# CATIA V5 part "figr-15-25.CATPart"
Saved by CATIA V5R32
Part number: Part1
Bounding box of the stored display mesh (mm): x -50 to 50, y -25 to 26, z -24 to 1
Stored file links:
  D:\PROJECTS\Project 2022\CATIA V5 6R 2022\Resources\Part Files\c15_catia_v5_6r2022_prt\figr-15-25.CATPart
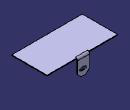
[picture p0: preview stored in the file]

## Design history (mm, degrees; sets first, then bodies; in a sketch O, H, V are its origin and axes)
SheetMetalParameters1: Thickness 1, BendRadius 2, KFactor 0.400515 {= log(min(100,max(20*SheetMetalParameters1.BendRadius,SheetMetalParameters1.Thickness)/SheetMetalParameters1.Thickness))/log(100)/2}, ReliefRadialLength 1, ReliefAxialLength 2, MinimumBendRadius 0
Body1 (main body)
  Sketch1 on xy-plane, origin (0, 0, 0), H (1, 0, 0), V (0, 1, 0)
    line L1 (-50, 25) -> (50, 25)
    line L2 (50, 25) -> (50, -25)
    line L3 (50, -25) -> (-50, -25)
    line L4 (-50, -25) -> (-50, 25)
    length L1 = 100
    distance V L2 = 50
    length L2 = 50
    distance H L3 = 25
    horizontal: L1 H, L3 H
    vertical: L2 V, L4 V
  Wall1: Thickness 1, Profile Sketch1
  Sketch2 on face of Wall1, origin (50, 25, 0), H (-1, 0, 0), V (0, 0, 1)
    line L1 (42.3549, 1) -> (42.3549, -19)
    point P2 (42.3549, -19)
    line L2 (42.3549, -19) -> (47.3549, -24)
    point P3 (47.3549, -24)
    line L3 (47.3549, -24) -> (54.3549, -24)
    point P4 (54.3549, -24)
    line L4 (54.3549, -24) -> (59.3549, -19)
    point P5 (59.3549, -19)
    line L5 (59.3549, -19) -> (59.3549, 1)
    line L6 (59.3549, 1) -> (42.3549, 1)
    reference projected line E1 (100, 1) -> (0, 1) from edge [face of Wall1 | face of Wall1]
    ellipse A1 centre (50.1164, -15.2153) semi-axes 5.0583, 2.1402 rotation 0
    length L5 = 20
    length L1 = 20
    length L3 = 7
    distance P4 L5 = 5
    distance P2 P3 H = 5
    distance L3 P5 = 5
    vertical: L1 V, L5 V
    horizontal: L3 H, L6 H
    coincidence: L6 E1
    parallelism: A1 L3
  d_NewWallOnEdge1: NewWallOnEdge_Edge edge [face of Wall1 | face of Wall1], NewWallOnEdge_WallProfile Sketch2, NewWallOnEdge_Length 100, NewWallOnEdge_HeightLimitOffset 0, NewWallOnEdge_WidthOffset1 0, NewWallOnEdge_WidthOffset2 0, NewWallOnEdge_Angle 0, NewWallOnEdge_BendRadiusValue 2 {= SheetMetalParameters1.BendRadius}, NewWallOnEdge_BendTable SheetMetalParameters1, KFacteur 0.400515 {= log(min(100,max(20*d_NewWallOnEdge1.Radius,SheetMetalParameters1.Thickness)/SheetMetalParameters1.Thickness))/log(100)/2}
